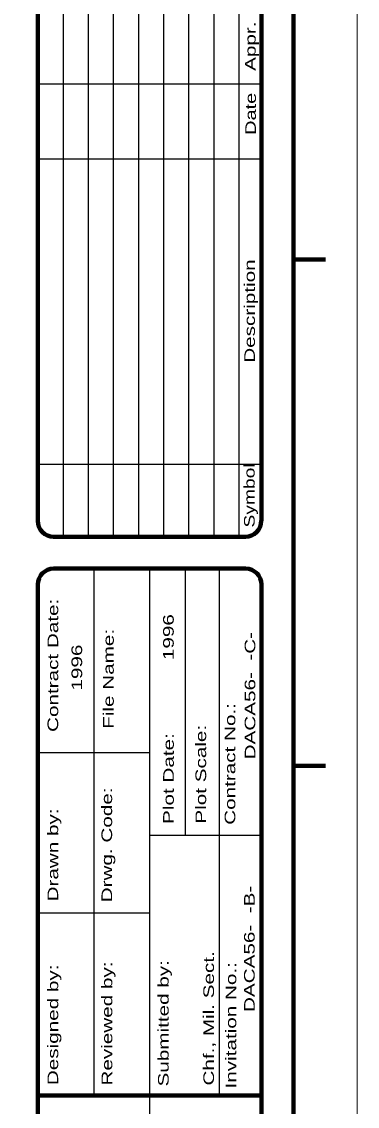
# Model space of a CAD drawing. Extents: x 55 to 190, y 198 to 264.
# Drawn here: x 140.29 to 146.59, y 221.76 to 242.12 of the extents above; entities that cross this region are included whole.
import ezdxf

# ---------------------------------------------------------------- set-up
doc = ezdxf.new("R2010")
doc.units = 0
doc.header["$LTSCALE"] = 0.1
doc.layers.add('1', color=7, linetype='Continuous', lineweight=25)
doc.layers.add('3', color=7, linetype='Continuous', lineweight=25)

msp = doc.modelspace()

# ---------------------------------------------------------------- linework, layer by layer
at = {"layer": '1'}
for p, q in [((141.0665, 251.8525), (141.0665, 232.4525)), ((141.5377, 251.8525), (141.5377, 232.4525)), ((142.009, 251.8525), (142.009, 232.4525)), ((142.4815, 251.8525), (142.4815, 232.4525)), ((142.9527, 251.8525), (142.9527, 232.4525)), ((143.4252, 251.8525), (143.4252, 232.4525)), ((143.8965, 251.8525), (143.8965, 232.4525)), ((144.3677, 251.8525), (144.3677, 232.4525)), ((140.5902, 240.9525), (144.7902, 240.9525)), ((140.5902, 239.5475), (144.7902, 239.5475)), ((140.5902, 233.8137), (144.7902, 233.8137)), ((141.6427, 231.855), (141.6427, 221.9637)), ((142.6927, 231.855), (142.6927, 215.4537)), ((143.3627, 231.855), (143.3627, 226.8512)), ((143.999, 231.855), (143.999, 221.9637)), ((142.6927, 228.3937), (140.5927, 228.3937)), ((142.6927, 226.8512), (144.7927, 226.8512)), ((140.5952, 225.3962), (142.6927, 225.3962))]:
    msp.add_line(p, q, dxfattribs=at)
at = {"layer": '1', "lineweight": 80}
for p, q in [((140.5902, 251.5525), (140.5902, 232.7525)), ((144.7902, 232.7525), (144.7902, 251.5525)), ((145.9927, 237.6525), (145.3927, 237.6525)), ((140.8902, 232.4525), (144.4902, 232.4525)), ((144.4927, 231.855), (140.8927, 231.855)), ((140.5927, 231.555), (140.5927, 215.7537)), ((144.7927, 215.7537), (144.7927, 231.555)), ((145.9927, 228.1525), (145.3927, 228.1525)), ((144.7927, 221.9637), (140.5927, 221.9637))]:
    msp.add_line(p, q, dxfattribs=at)
at = {"layer": '1', "lineweight": 13}
msp.add_lwpolyline([(62.4915, 257.8525), (146.5927, 257.8525), (146.5927, 198.4512), (62.4915, 198.4512)], close=True, dxfattribs=at)
at = {"layer": '1', "lineweight": 80}
msp.add_lwpolyline([(65.1915, 256.6525), (145.3927, 256.6525), (145.3927, 199.6512), (65.1915, 199.6512)], close=True, dxfattribs=at)
for centre, start, end in [((140.89, 232.7519), 180, 270), ((144.4899, 232.7519), 270, 0), ((140.8922, 231.5539), 90, 180), ((144.4922, 231.5539), 0, 90)]:
    msp.add_arc(centre, 0.3, start, end, dxfattribs=at)

# ---------------------------------------------------------------- texts
at = {"layer": '1'}
for s, width, p in [('Appr.', 1.45, (144.684, 241.195)), ('Date', 1.4, (144.689, 239.9937)), ('Description', 1.45, (144.6702, 235.7175)), ('Symbol', 1.35, (144.6652, 232.625)), ('Contract Date:', 1.45, (140.9752, 228.7887)), ('File Name:', 1.45, (142.019, 228.8475)), ('DACA56-  -C-    ', 1.45, (144.6777, 228.2737)), ('       1996', 1.45, (141.4252, 228.8112)), ('Contract No.:', 1.45, (144.3015, 227.0462)), ('Plot Scale:', 1.45, (143.754, 227.0675)), ('Plot Date:', 1.45, (143.1465, 227.0625)), ('Drwg. Code:', 1.45, (141.9877, 225.5912)), ('Drawn by:', 1.45, (140.9752, 225.6075)), ('DACA56-  -B-    ', 1.45, (144.6652, 223.5325)), ('Chf., Mil. Sect.', 1.45, (143.9015, 222.1525)), ('Designed by:', 1.45, (140.9752, 222.16)), ('Reviewed by:', 1.45, (141.9915, 222.1525)), ('Submitted by:', 1.45, (143.0502, 222.135)), ('Invitation No.:', 1.45, (144.319, 222.0975))]:
    msp.add_text(s, height=0.2, rotation=90, dxfattribs=dict(at, width=width)).set_placement(p)
at = {"layer": '3', "width": 1.45}
msp.add_text('       1996', height=0.2, rotation=90, dxfattribs=at).set_placement((143.1452, 229.3825))
msp.add_text('       1996', height=0.2, rotation=90, dxfattribs=at).set_placement((143.1452, 229.3825))

doc.saveas('drawing.dxf')
